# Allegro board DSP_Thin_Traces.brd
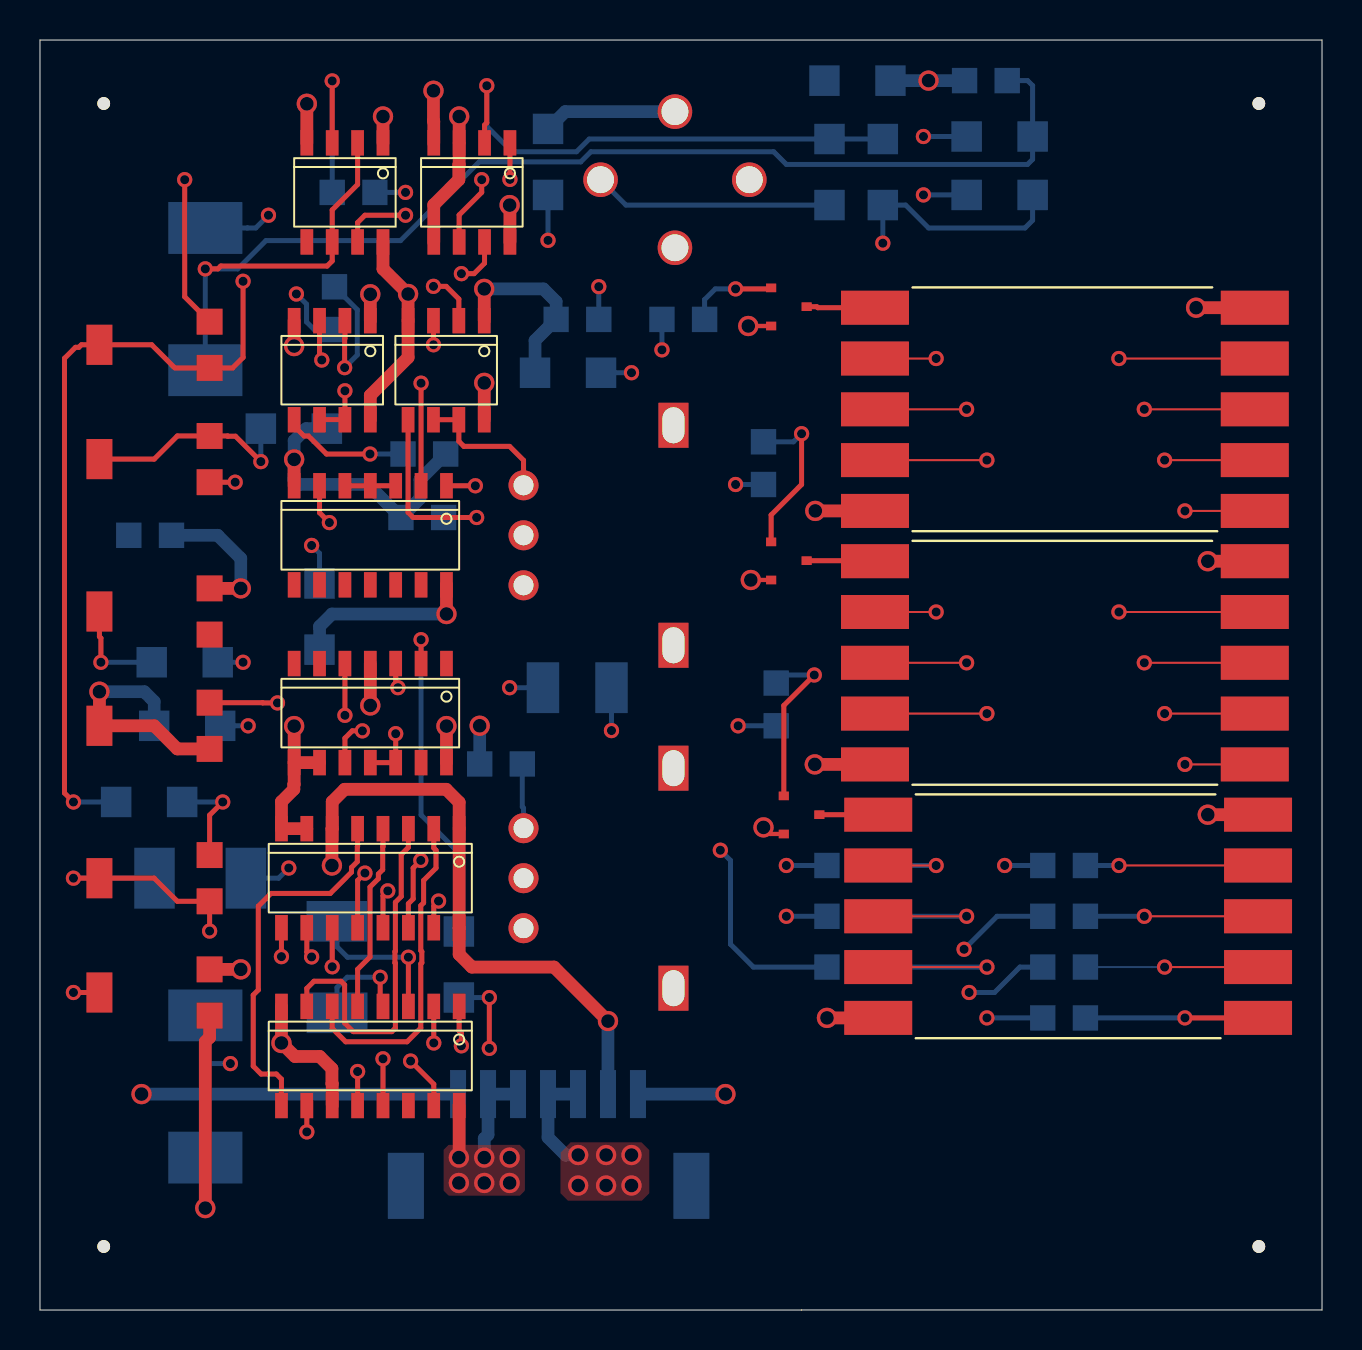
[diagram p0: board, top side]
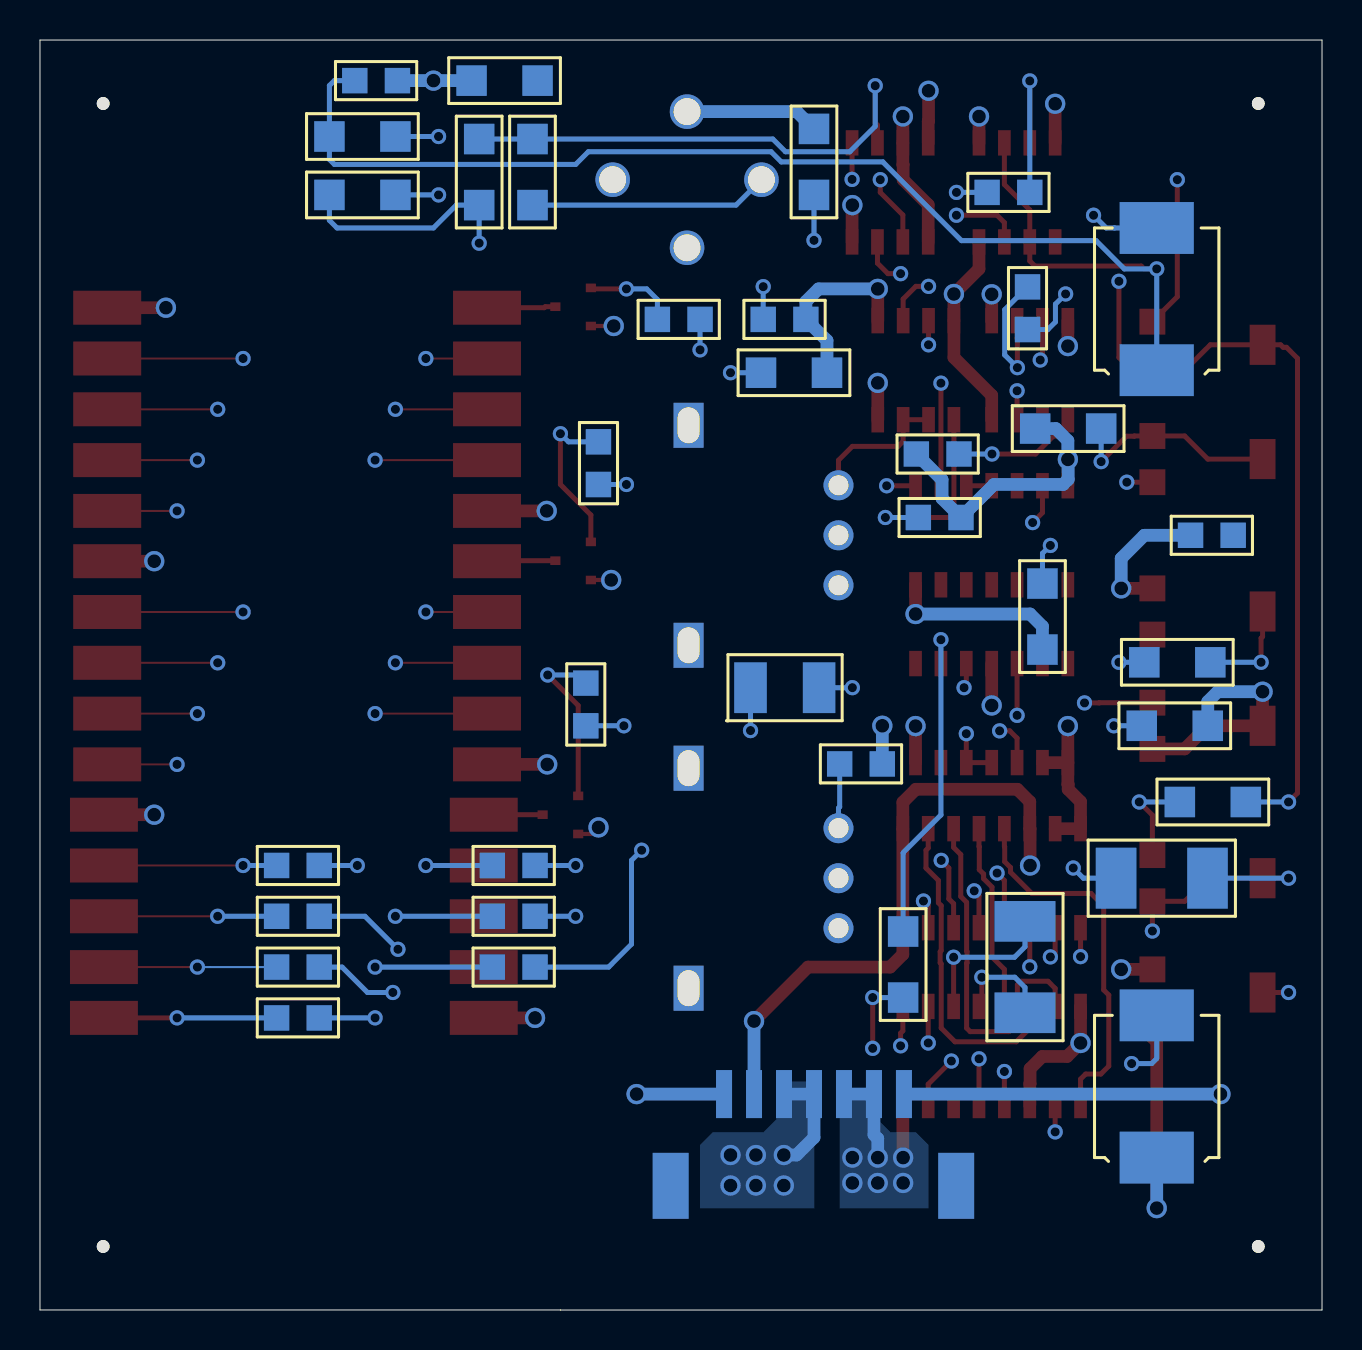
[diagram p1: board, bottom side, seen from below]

Outline 64.13 x 63.5 mm; copper layers: TOP, LAYER_2, LAYER_3, LAYER_4, LAYER_5, BOTTOM. Coordinates in mm from the lower left corner of the outline.
Outline path: 0,63.5 0,0 38.1,0 64.13,0 64.13,63.5 0,63.5

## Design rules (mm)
constraint set DEFAULT: 

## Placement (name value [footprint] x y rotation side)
C1  -  [SMC1210]  28.59 31.12 180 bottom
C2  -  [SMC1812]  5.73 21.59 0 bottom
C3  -  [SMC0805]  48.39 61.47 180 bottom
C4  -  [SMC0805]  4.45 38.74 0 bottom
C5  -  [SMC0805]  14.62 55.88 0 bottom
C6  -  [SMC0805]  27.95 49.53 180 bottom
C7  -  [SMC0805]  18.16 42.8 0 bottom
C8  -  [SMC0805]  14.73 49.02 90 bottom
C9  -  [SMC0805]  24.13 27.31 180 bottom
C10  -  [SMC0805]  20.19 39.63 180 bottom
C11  -  [SMC1812]  14.86 14.86 90 bottom
D1  -  [SMDO214AB12]  8.27 46.99 90 bottom
D2  -  [SMDO214AB12]  8.27 7.62 90 bottom
J1  -  [MDPC2A]  31.76 56.52 0 top
J2  -  [MLX1_5MM7P]  25.41 10.8 180 bottom
LED1  -  [LED-DISPLAY]  51.27 45.03 90 top
LED2  -  [LED-DISPLAY]  51.44 19.69 90 top
LED3  -  [LED-DISPLAY]  51.27 32.36 90 top
NOREF  -  [unnamed]  60.97 3.18 0 top
NOREF#2  -  [unnamed]  3.19 60.33 0 top
NOREF#3  -  [unnamed]  60.97 60.33 0 top
NOREF#4  -  [unnamed]  3.19 3.18 0 top
Q1  -  [SOT23]  37.47 50.17 0 top
Q2  -  [SOT23]  38.1 24.77 0 top
Q3  -  [SOT23]  37.47 37.47 0 top
R1  -  [3314G-]  5.73 42.55 270 top
R2  -  [SMR1206]  11.05 44.07 0 bottom
R3  -  [SMR1206]  39.5 55.25 90 bottom
R4  -  [3314G-]  5.73 34.93 270 top
R5  -  [SMR1206]  8.89 32.39 180 bottom
R6  -  [SMR1206]  42.16 58.55 270 bottom
R7  -  [SMR1206]  49.66 55.75 180 bottom
R8  -  [3314G-]  5.73 48.26 270 top
R9  -  [SMR1206]  3.81 25.4 0 bottom
R10  -  [3314G-]  5.73 21.59 270 top
R11  -  [SMR1206]  42.55 61.47 180 bottom
R12  -  [SMR1206]  25.41 59.06 270 bottom
R13  -  [SMR1206]  28.07 46.86 180 bottom
R14  -  [SMR1206]  20.95 18.92 270 bottom
R15  -  [3314G-]  5.73 15.88 270 top
R16  -  [3314G-]  5.73 29.21 270 top
R17  -  [SMR1206]  46.36 58.68 0 bottom
R18  -  [SMR1206]  5.71 29.21 0 bottom
R19  -  [RK09L]  27.94 38.74 270 top
R20  -  [RK09L]  27.94 21.59 270 top
R21  -  [SMR1206]  13.98 33.02 90 bottom
R22  -  [SMR0805]  50.16 22.23 0 bottom
R23  -  [SMR0805]  39.37 22.23 0 bottom
R24  -  [SMR0805]  39.37 19.69 0 bottom
R25  -  [SMR0805]  39.37 17.15 0 bottom
R26  -  [SMR0805]  50.16 19.69 0 bottom
R27  -  [SMR0805]  50.16 17.15 0 bottom
R28  -  [SMR0805]  50.16 14.61 0 bottom
R29  -  [SMR0805]  31.12 49.53 0 bottom
R30  -  [SMR0805]  36.83 29.21 90 bottom
R31  -  [SMR0805]  36.2 41.28 90 bottom
U2  ***  [SOIC8]  21.6 55.88 270 top
U3  ***  [SOIC14]  16.52 29.85 270 top
U4  ***  [SOIC14]  16.52 38.74 270 top
U5  ***  [SOIC8]  15.25 55.88 270 top
U6  ***  [SOIC8]  20.32 46.99 270 top
U7  ***  [SOIC8]  14.62 46.99 270 top
U8  ***  [SOIC16]  16.52 12.7 270 top
U9  ***  [SOIC16]  16.52 21.59 270 top

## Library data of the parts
C1 = 1000PF
C2 = 100PF
C3 C6 C9 = 1UF
C4 C5 C7 C8 C10 = 01UF
C11 = 001UF
D1 D2 = 1N914
J1 = MDPC2A
J2 = 7PINMLX
LED1-LED3 = LED-DISP
Q1-Q3 = 2N1305
R1 = IK-POT
R2 R7 R12 R13 R21 = RES10K
R3 R5 R6 R11 = RES100K
R4 = 10K-POT
R8 = 1M-POT
R9 = RES180K
R10 R15 = 50K-POT
R14 = RES510K
R16 = 3K-POT
R17 = RES15K
R18 = RES20K
R19 = 10K-VC
R20 = 1K-VC
R22-R28 = RES220
R29-R31 = RES1K
U2 = OPAMP
U3 = TVC-9400
U4 = NAND00
U5-U7 = 555
U8 = 3D-BCD
U9 = MC14543

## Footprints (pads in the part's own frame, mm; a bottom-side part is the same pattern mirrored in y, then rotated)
3314G-
  rect 2.007x1.295 smd: 1(0,-2.756)
  rect 1.295x1.295 smd: 2(-1.156,2.756) 3(1.156,2.756)
LED-DISPLAY
  rect 1.7x3.4 smd: 1(-5.08,-9.5) 2(-2.54,-9.5) 3(0,-9.5) 4(2.54,-9.5) 5(5.08,-9.5) 6(5.08,9.5) 7(2.54,9.5) 8(0,9.5) 9(-2.54,9.5) 10(-5.08,9.5)
MDPC2A
  round 1.727 hole 1.346: 1(0,-3.404) 2(0,3.404) 3(-3.721,0) 4(3.721,0)
MLX1_5MM7P
  rect 1.8x3.3 smd: (-7.172,-4.588) (7.112,-4.588)
  rect 0.8x2.4 smd: 1(-4.5,0) 2(-3,0) 3(-1.5,0) 4(0,0) 5(1.5,0) 6(3,0) 7(4.5,0)
RK09L
  rect 2.25x1.5 hole 1.8x1.1: (-5.5,3.75) (5.5,3.75)
  round 1.5 hole 1: 1(0,-3.75) 2(-2.5,-3.75) 3(2.5,-3.75)
SMC0805
  rect 1.27x1.27 smd: 1(0,0) 2(2.134,0)
SMC1210
  rect 1.626x2.54 smd: 1(0,0) 2(3.429,0)
SMC1812
  rect 2.032x3.048 smd: 1(0,0) 2(4.572,0)
SMDO214AB12
  rect 2.591x3.708 smd: 1(0,0) 2(7.112,0)
SMR0805
  rect 1.27x1.27 smd: 1(0,0) 2(2.134,0)
SMR1206
  rect 1.524x1.524 smd: 1(0,0) 2(3.302,0)
SOIC8
  rect 1.27x0.635 smd: 1(-2.477,1.905) 2(-2.477,0.635) 3(-2.477,-0.635) 4(-2.477,-1.905) 5(2.477,-1.905) 6(2.477,-0.635) 7(2.477,0.635) 8(2.477,1.905)
SOIC14
  rect 1.27x0.635 smd: 1(-2.477,3.81) 2(-2.477,2.54) 3(-2.477,1.27) 4(-2.477,0) 5(-2.477,-1.27) 6(-2.477,-2.54) 7(-2.477,-3.81) 8(2.477,-3.81) 9(2.477,-2.54) 10(2.477,-1.27) 11(2.477,0) 12(2.477,1.27) 13(2.477,2.54) 14(2.477,3.81)
SOIC16
  rect 1.27x0.635 smd: 1(-2.477,4.445) 2(-2.477,3.175) 3(-2.477,1.905) 4(-2.477,0.635) 5(-2.477,-0.635) 6(-2.477,-1.905) 7(-2.477,-3.175) 8(-2.477,-4.445) 9(2.477,-4.445) 10(2.477,-3.175) 11(2.477,-1.905) 12(2.477,-0.635) 13(2.477,0.635) 14(2.477,1.905) 15(2.477,3.175) 16(2.477,4.445)
SOT23
  rect 0.508x0.432 smd: 1(-0.889,0.94) 2(-0.889,-0.965) 3(0.889,0)
unnamed
  round 0.635 hole 3.175 unplated: (0,0)

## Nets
+5V: D2.1 J1.2 J2.5 J2.6 LED1.10 LED2.10 LED3.10 Q1.2 Q2.2 Q3.2 R12.1 R15.3 R16.1 R16.3 R18.1 R19.1 R19.3 R20.1 R20.3 R21.1 U3.14 U4.14 U5.4 U5.8 U6.4 U6.8 U7.4 U7.8 U8.16
+15V: J2.7 U2.8
-5V: J2.2 U3.4 U9.1 U9.6 U9.16
-15V: J2.1 U2.4
GND: C3.2 C4.2 C6.2 C7.2 C9.2 C10.2 J2.3 J2.4 LED1.5 LED2.5 LED3.5 R2.2 R4.2 R11.1 R13.2 R15.2 U2.3 U2.5 U3.8 U3.9 U4.7 U5.1 U6.1 U7.1 U8.8 U8.11 U9.7 U9.8
A: R31.1 U8.2
B: R30.1 U8.1
C: R29.1 U8.15
CLK1: C5.1 U4.2 U5.3
DSP0: LED1.1 LED2.1 LED3.1 R28.2
DSP1: LED1.2 LED2.2 LED3.2 R27.2
DSP2: LED1.3 LED2.3 LED3.3 R26.2
DSP3: LED1.4 LED2.4 LED3.4 R22.2
DSP4: LED1.9 LED2.9 LED3.9 R25.2
DSP5: LED1.8 LED2.8 LED3.8 R24.2
DSP6: LED1.7 LED2.7 LED3.7 R23.2
IN01: U4.6 U8.12
N001: U4.3 U4.4 U4.5
N002: C3.1 D1.1 R17.2 U5.2 U5.6
N003: D1.2 U5.7
N004: R16.2 R17.1
N005: R12.2 U3.10 U4.1
N006: Q1.1 R29.2
N007: Q2.1 R30.2
N007A: Q3.1 R31.2
N008: LED1.6 Q1.3
N008A: LED2.6 Q2.3
N008B: LED3.6 Q3.3
N009: R13.1 R14.1 U3.2
N010: R14.2 R15.1
N011: C1.1 U3.11 U3.12
N012: C2.2 U3.5
N013: C1.2 C2.1 R10.1 R10.3 U3.3
N014: R8.1 R8.3 R9.1 U2.7
N015: R9.2 R10.2
N016: R7.2 R8.2 U2.6
N017: R6.2 R7.1 U2.1
N018: R3.2 R5.1 R6.1 U2.2
N019: R4.1 R5.2
N100: C10.1 U6.5
N101: C7.1 U7.5
PRB1: J1.1 R1.3
PRB2: J1.3 R3.1
PRESET1: C5.2 D2.2 R18.2 U6.2
PRESET2: C8.2 R21.2 U7.2
PSP0: R28.1 U9.9
PSP1: R27.1 U9.10
PSP2: R26.1 U9.11
PSP3: R25.1 U9.12
PSP4: R24.1 U9.13
PSP5: R23.1 U9.14
PSP6: R22.1 U9.15
PST+: C11.1 U8.4
PST-: C11.2 U8.3
SET1: C6.1 R19.2 U6.6 U6.7
SET2: C9.1 R20.2 U7.6 U7.7
SNSR1: R1.1 R1.2 R2.1
SP0: U8.9 U9.5
SP01: U8.7 U9.3
SP02: U8.6 U9.2
SP03: U8.5 U9.4
T1: U7.3 U8.13
T2: C8.1 U6.3 U8.10

Pads without a net: C4 1; J1 4; R4 3; R11 2; U3 1 6 7 13; U4 8 9 10 11 12 13; U5 5; U8 14

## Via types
v1: diameter 0.762, hole 0.457, TOP to BOTTOM, 100 vias
v2: diameter 1.016, hole 0.686, TOP to BOTTOM, 47 vias

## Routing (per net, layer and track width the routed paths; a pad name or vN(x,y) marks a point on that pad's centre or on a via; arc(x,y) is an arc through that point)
+5V: length 76.3
  TOP w0.21: v2(35.56,36.5) Q3.2 ; Q2.2 36.53,23.8 v2(36.2,24.13) ; v2(35.43,49.2) Q1.2
  TOP w0.635: U3.14 v2(20.33,29.2) ; U4.14 v2(20.33,34.8) ; U6.8 v2(22.23,46.36) ; U5.8 17.16,52.06 v2(18.41,50.8) U6.4 18.41,47.63 16.52,45.74 U7.8 ; U5.4 v2(13.35,60.31) ; LED3.10 v2(38.76,27.28) ; U7.4 v2(12.71,48.2) ; v2(2.97,30.91) R16.1 R18.1 6.87,28.06 R16.3 ; 41.93,14.61 v2(39.37,14.61) ; v2(20.95,7.62) 20.97,7.64 U8.16 ; LED1.10 v2(38.79,39.95) ; v2(8.27,5.1) 8.27,13.41 8.49,13.63 R15.3
  BOTTOM w0.635: J2.5 J2.6 22.41,8.76 22.23,8.57 v2(22.23,7.62) ; D2.1 v2(8.27,5.1) ; R21.1 13.98,34.18 14.61,34.8 v2(20.33,34.8) ; R12.1 26.28,59.92 J1.2 ; v2(2.97,30.91) 5.22,30.91 5.71,30.42 R18.1
  vias: v2(20.95,6.35) v2(22.23,6.35) v2(23.5,7.62) v2(23.5,6.35)
+15V: length 81.4
  TOP w0.635: v2(23.5,55.25) 23.51,55.23 U2.8
  LAYER_4 w0.635: v2(5.08,10.8) 5.08,54.61 5.97,55.5 7.5,55.5 7.88,55.88 17.01,55.88 17.91,56.78 18.66,56.78 20.2,55.25 v2(23.5,55.25)
  BOTTOM w0.635: J2.7 v2(5.08,10.8)
-5V: length 43.4
  TOP w0.635: U3.4 v2(16.52,30.23) ; v2(14.61,22.23) 14.61,24.05 U9.6 14.62,25.42 15.24,26.04 20.32,26.04 20.97,25.39 U9.1 U9.16 20.97,17.78 21.6,17.15 25.71,17.15 v2(28.41,14.45)
  LAYER_3 w0.635: v2(16.52,30.23) 16.02,30.74 14.67,30.74 13.93,30 13.93,22.9 v2(14.61,22.23)
  BOTTOM w0.635: J2.2 v2(28.41,14.45)
-15V: length 145.8
  TOP w0.635: U2.4 19.7,59.44 19.68,59.45 v2(19.68,60.96)
  LAYER_3 w0.635: v2(19.68,60.96) 20.95,62.23 43.76,62.23 44.02,62.5 44.88,62.5 45.14,62.23 57.15,62.23 57.78,61.6 57.78,57.79 58.42,57.15 62.23,57.15 62.87,56.52 62.87,6.99 62.23,6.35 58.42,6.35 57.78,5.72 57.78,1.91 57.15,1.27 37.8,1.27 arc(37.49,1.33) 37.23,1.51 34.53,4.21 arc(34.35,4.47) 34.29,4.78 v2(34.29,10.8)
  BOTTOM w0.635: 29.91,10.8 v2(34.29,10.8)
GND: length 76.5
  TOP w0.635: R4.2 v2(10.05,36.08) ; U9.7 U9.8 12.08,25.42 12.7,26.04 12.7,26.28 12.71,26.29 U3.8 ; U2.5 19.7,55.26 20.95,56.52 20.95,57.26 20.97,57.28 U2.3 v2(20.97,59.68) ; U3.8 U3.9 ; U3.8 v2(12.71,29.2) ; U6.1 v2(22.23,51.06) ; U8.8 v2(12.08,13.35) 12.75,12.68 13.99,12.68 14.61,12.07 14.61,11.32 14.62,11.3 U8.11 ; U7.1 v2(16.52,50.79) ; LED1.5 v2(57.84,50.11) ; U5.1 v2(17.16,59.68) ; R15.2 v2(10.05,17.03) ; LED2.5 v2(58.42,24.77) ; U4.7 v2(12.71,42.53) ; LED3.5 v2(58.42,37.44)
  BOTTOM w0.635: v2(10.05,36.08) 10.05,37.58 8.89,38.74 C4.2 ; R13.2 24.77,48.47 C6.2 25.82,50.42 25.19,51.06 v2(22.23,51.06) ; C7.2 19.01,41.51 19.01,40.57 C10.2 16.41,41.28 12.95,41.28 12.7,41.53 12.7,42.52 v2(12.71,42.53) 12.71,43.47 13.32,44.07 R2.2 ; 26.91,7.76 v2(26.92,7.75) 26.29,7.75 25.41,8.62 J2.4 J2.3 ; C3.2 v2(44.45,61.47) R11.1 ; v2(22,29.21) C9.2
  vias: v2(26.92,6.22) v2(28.32,7.75) v2(28.32,6.22) v2(29.59,7.75) v2(29.59,6.22)
A: length 39.1
  TOP w0.25: U8.2 v1(19.7,13.35)
  LAYER_2 w0.25: v1(34.8,41.28) 33.91,40.39 33.91,26.04 24.51,16.64 21.54,16.64 19.7,14.8 v1(19.7,13.35)
  BOTTOM w0.25: R31.1 v1(34.8,41.28)
B: length 26.5
  TOP w0.25: U8.1 20.97,13.95 21.08,13.84 v1(21.08,13.21)
  LAYER_2 w0.25: v1(21.08,13.21) 22.35,14.48 23.75,14.48 34.93,25.66 v1(34.93,29.21)
  BOTTOM w0.25: R30.1 v1(34.93,29.21)
C: length 46.6
  TOP w0.25: U8.15 19.7,11.29 v1(18.54,12.45)
  LAYER_2 w0.25: v1(31.12,48.01) 31.12,46.61 30.23,45.72 30.23,23.37 24.51,17.65 21.84,17.65 18.54,14.35 v1(18.54,12.45)
  BOTTOM w0.25: R29.1 v1(31.12,48.01)
CLK1: length 31.9
  TOP w0.25: v1(14.62,61.45) U5.3 ; U4.2 v1(19.06,46.34)
  LAYER_2 w0.25: v1(19.06,46.34) 20.41,47.69 20.41,54.78 14.62,60.57 v1(14.62,61.45)
  BOTTOM w0.25: C5.1 v1(14.62,61.45)
DSP0: length 41
  TOP w0.101: LED1.1 v1(57.28,39.95) ; LED3.1 v1(57.28,27.28)
  TOP w0.25: LED2.1 v1(57.28,14.61)
  LAYER_2 w0.101: v1(57.28,14.61) v1(57.28,27.28) v1(57.28,39.95)
  BOTTOM w0.25: R28.2 v1(57.28,14.61)
DSP1: length 43
  TOP w0.101: LED2.2 57.02,17.15 57.02,17.15 v1(56.26,17.15) ; LED1.2 v1(56.26,42.49) ; LED3.2 v1(56.26,29.82)
  LAYER_2 w0.101: v1(56.26,17.15) v1(56.26,29.82) v1(56.26,42.49)
  BOTTOM w0.101: R27.2 55.63,17.15 55.63,17.15 v1(56.26,17.15)
DSP2: length 45
  TOP w0.101: LED1.3 v1(55.24,45.03) ; LED3.3 v1(55.24,32.36) ; LED2.3 v1(55.24,19.69)
  LAYER_2 w0.101: v1(55.24,45.03) v1(55.24,32.36) v1(55.24,19.69)
  BOTTOM w0.25: R26.2 v1(55.24,19.69)
DSP3: length 47.6
  TOP w0.101: LED2.4 v1(53.98,22.23) ; LED3.4 v1(53.98,34.9) ; LED1.4 v1(53.98,47.57)
  LAYER_2 w0.101: v1(53.98,22.23) v1(53.98,34.9) v1(53.98,47.57)
  BOTTOM w0.25: R22.2 v1(53.98,22.23)
DSP4: length 47.9
  TOP w0.101: 41.93,17.15 v1(47.37,17.15) ; LED3.9 v1(47.37,29.82) ; LED1.9 v1(47.37,42.49)
  LAYER_2 w0.101: v1(47.37,42.49) v1(47.37,29.82) v1(47.37,17.15)
  BOTTOM w0.25: R25.2 v1(47.37,17.15)
DSP5: length 43.8
  TOP w0.101: LED1.8 v1(46.36,45.03) ; 41.93,19.69 v1(46.36,19.69) ; LED3.8 v1(46.36,32.36)
  LAYER_2 w0.101: v1(46.36,19.69) v1(46.36,32.36) v1(46.36,45.03)
  BOTTOM w0.25: R24.2 v1(46.36,19.69)
DSP6: length 37.7
  TOP w0.101: LED1.7 v1(44.83,47.57) ; LED3.7 v1(44.83,34.9) ; 41.93,22.23 v1(44.83,22.23)
  LAYER_2 w0.101: v1(44.83,22.23) v1(44.83,34.9) v1(44.83,47.57)
  BOTTOM w0.25: R23.2 v1(44.83,22.23)
IN01: length 34.3
  TOP w0.25: U4.6 13.98,39.87 v1(14.48,39.37) ; U8.12 v1(15.89,11.92)
  LAYER_2 w0.25: v1(15.89,11.92) 15.89,21.26 15.58,21.57 15.58,22.12 15.89,22.43 15.89,25.54 18.58,28.23 18.58,31.84 14.48,35.94 v1(14.48,39.37)
N001: length 2.5
  TOP w0.25: U4.5 U4.4 U4.3
N002: length 67.3
  TOP w0.25: v1(8.27,52.06) 8.9,52.06 9.04,52.2 14.37,52.2 14.62,52.45 U5.6 14.62,55.01 15.89,56.28 U5.2
  BOTTOM w0.25: D1.1 v1(8.27,52.06) 9.89,52.06 11.3,53.47 18.03,53.47 21.97,57.41 27.05,57.41 27.56,57.91 36.7,57.91 37.34,57.28 49.4,57.28 49.66,57.53 R17.2 49.66,61.22 49.41,61.47 C3.1
N003: length 13.8
  TOP w0.25: v1(18.29,54.74) 16.26,54.74 15.89,54.37 U5.7
  LAYER_5 w0.25: v1(18.29,54.74) v1(11.43,54.74)
  BOTTOM w0.25: D1.2 10.38,54.1 10.38,54.1 10.79,54.1 v1(11.43,54.74)
N004: length 72.8
  TOP w0.25: v1(11.88,30.35) 11.15,30.35 11.13,30.37 R16.2
  LAYER_5 w0.25: v1(11.88,30.35) 11.88,27.87 14.08,25.67 40.79,25.67 43.94,28.83 43.94,54.23 44.82,55.11 44.82,58.05 v1(44.2,58.68)
  BOTTOM w0.25: R17.1 v1(44.2,58.68)
N005: length 37.6
  TOP w0.25: v1(16.13,28.96) 15.62,28.96 15.25,28.59 U3.10 ; U4.1 v1(21.78,41.21)
  LAYER_2 w0.25: v1(25.41,53.48) 25.41,47.51 21.78,43.88 v1(21.78,41.21)
  LAYER_5 w0.25: v1(21.78,41.21) 21.14,41.21 21.08,41.15 19.3,41.15 14.58,36.43 14.58,29.46 15.08,28.96 v1(16.13,28.96)
  BOTTOM w0.25: R12.2 v1(25.41,53.48)
N006: length 4.6
  TOP w0.25: Q1.1 36.53,51.06 v1(34.8,51.06)
  BOTTOM w0.25: R29.2 33.25,50.52 33.78,51.06 v1(34.8,51.06)
N007: length 8.7
  TOP w0.25: v1(38.73,31.75) 37.21,30.23 Q2.1
  BOTTOM w0.25: R30.2 37.24,31.75 v1(38.73,31.75)
N007A: length 8.1
  TOP w0.25: Q3.1 36.58,39.75 38.1,41.28 v1(38.1,43.82)
  BOTTOM w0.25: v1(38.1,43.82) 37.69,43.41 R31.2
N008: length 3.4
  TOP w0.25: LED1.6 38.91,50.11 38.86,50.17 Q1.3
N008A: length 2.9
  TOP w0.25: Q2.3 LED2.6
N008B: length 3.4
  TOP w0.25: Q3.3 41.75,37.47 LED3.6
N009: length 38
  TOP w0.25: U3.2 v1(19.06,33.51)
  LAYER_2 w0.25: v1(29.59,46.86) 27.18,46.86 22.86,42.55 22.86,35.94 20.43,33.51 v1(19.06,33.51)
  BOTTOM w0.25: R14.1 20.95,22.86 19.06,24.75 v1(19.06,33.51) ; v1(29.59,46.86) R13.1
N010: length 27.4
  TOP w0.25: v1(22.48,13.08) v1(22.48,15.62) ; 2.97,15.88 v1(1.67,15.88)
  LAYER_5 w0.25: v1(1.67,15.88) 2.12,15.43 2.12,15.28 3.21,14.19 21.37,14.19 v1(22.48,13.08)
  BOTTOM w0.25: R14.2 v1(22.48,15.62)
N011: length 16.1
  TOP w0.25: v1(17.79,28.82) U3.12 U3.11
  LAYER_5 w0.25: v1(28.59,28.97) 27.94,28.32 19.18,28.32 18.68,28.82 v1(17.79,28.82)
  BOTTOM w0.25: C1.1 v1(28.59,28.97)
N012: length 13.7
  TOP w0.25: U3.5 v1(15.25,29.73)
  LAYER_2 w0.25: v1(15.25,29.73) 15.25,26.69 12.45,23.88 v1(12.45,22.1)
  BOTTOM w0.25: C2.2 11.94,21.59 v1(12.45,22.1)
N013: length 38.8
  TOP w0.25: U3.3 17.79,31.23 v1(17.91,31.12) ; v1(8.49,18.95) R10.3 6.87,20.44 5.71,21.59 R10.1 v1(1.67,21.59)
  LAYER_2 w0.25: v1(8.49,18.95) 8.49,22.84 14.1,28.45 14.1,29.72 15.49,31.12 v1(17.91,31.12)
  LAYER_5 w0.25: v1(23.5,31.12) v1(17.91,31.12)
  BOTTOM w0.25: C2.1 v1(1.67,21.59) ; v1(23.5,31.12) 23.75,31.12 C1.2
N014: length 52.4
  TOP w0.25: U2.7 22.24,52.34 21.71,51.82 v1(21.08,51.82) ; v1(1.67,25.4) 1.23,25.85 1.23,47.58 1.78,48.13 1.95,48.13 2.07,48.26 R8.1 5.59,48.26 6.74,47.11 R8.3 9.64,47.11 10.16,47.63 v1(10.16,51.44)
  LAYER_5 w0.25: v1(10.16,51.44) 11.3,52.58 20.32,52.58 v1(21.08,51.82)
  BOTTOM w0.25: R9.1 v1(1.67,25.4)
N015: length 5
  TOP w0.25: R10.2 8.49,24.74 v1(9.14,25.4)
  BOTTOM w0.25: R9.2 v1(9.14,25.4)
N016: length 52.2
  TOP w0.25: v1(7.24,56.52) 7.24,50.66 R8.2 ; U2.6 20.97,54.75 22.1,55.88 v1(22.1,56.52)
  LAYER_5 w0.25: v1(44.2,55.75) 41.53,58.42 24,58.42 v1(22.1,56.52) 18.6,56.52 18.57,56.55 18.01,56.55 17.97,56.52 v1(7.24,56.52)
  BOTTOM w0.25: R7.2 v1(44.2,55.75)
N017: length 33.1
  TOP w0.25: U2.1 v1(23.51,56.53)
  LAYER_5 w0.25: v1(42.16,53.34) 40.51,54.99 27.18,54.99 25.64,56.53 v1(23.51,56.53)
  BOTTOM w0.25: R7.1 49.66,54.48 49.28,54.1 44.45,54.1 43.31,55.25 R6.2 v1(42.16,53.34)
N018: length 68.7
  TOP w0.25: U2.2 22.24,59.25 22.35,59.36 v1(22.35,61.22)
  LAYER_2 w0.25: v1(10.16,32.39) 9.02,33.53 9.02,58.42 12.83,62.23 21.34,62.23 v1(22.35,61.22)
  BOTTOM w0.25: v1(22.35,61.22) 22.35,59.18 23.62,57.91 26.84,57.91 27.48,58.55 R3.2 R6.1 ; v1(10.16,32.39) R5.1
N019: length 5.1
  TOP w0.25: R4.1 2.97,33.67 3.05,33.6 v1(3.05,32.39)
  BOTTOM w0.25: R5.2 v1(3.05,32.39)
N100: length 9.8
  TOP w0.25: v1(21.84,39.63) 18.67,39.63 18.41,39.88 U6.5
  BOTTOM w0.25: C10.1 v1(21.84,39.63)
N101: length 6.3
  TOP w0.25: U7.5 12.71,44.2 13.21,43.7 13.43,43.7 14.33,42.8 v1(16.51,42.8)
  BOTTOM w0.25: C7.1 v1(16.51,42.8)
PRB1: length 39.8
  TOP w0.25: R1.3 v1(9.77,41.39)
  LAYER_5 w0.25: J1.1 30.77,54.1 25.68,54.1 25.67,54.11 25.16,54.11 25.15,54.1 8.64,54.1 7.11,52.58 7.11,43.05 8.78,41.39 v1(9.77,41.39)
PRB2: length 12
  BOTTOM w0.25: R3.1 29.31,55.25 J1.3
PRESET1: length 66.1
  TOP w0.25: v1(19.68,51.18) 20.32,51.18 20.95,50.55 U6.2
  LAYER_2 w0.25: v1(18.29,55.88) 19.68,54.48 v1(19.68,51.18) ; v1(10.41,29.21) 7.3,26.1 7.3,16.45 9.53,14.23 v1(9.53,12.32)
  LAYER_5 w0.25: v1(19.68,51.18) 19.23,51.64 11.76,51.64 9.91,49.79 9.91,42.2 10.54,41.57 10.54,37.76 9.21,36.43 9.21,30.42 v1(10.41,29.21)
  BOTTOM w0.25: R18.2 v1(10.41,29.21) ; C5.2 v1(18.29,55.88) ; D2.2 8.27,12.57 8.52,12.32 v1(9.53,12.32)
PRESET2: length 18.8
  TOP w0.25: U7.2 15.25,48.58 15.24,48.56 v1(15.24,47.12)
  LAYER_2 w0.25: v1(15.24,47.12) 14.58,46.46 14.58,41.76 13.59,40.77 v1(13.59,38.23)
  BOTTOM w0.25: R21.2 13.98,37.83 v1(13.59,38.23) ; 14.73,51.16 15.88,50.01 15.88,47.75 v1(15.24,47.12)
PSP0: length 43.2
  TOP w0.25: U9.9 v1(12.08,17.67)
  LAYER_5 w0.25: v1(12.08,17.67) 12.08,17.03 12.06,17.02 12.06,15.5 12.57,14.99 21.72,14.99 23.5,13.21 40.89,13.21 42.29,14.61 v1(47.37,14.61)
  BOTTOM w0.25: R28.1 v1(47.37,14.61)
PSP1: length 41.8
  TOP w0.25: v1(13.59,17.65) 13.35,17.89 U9.10
  LAYER_5 w0.25: v1(46.48,15.88) 37.47,15.88 35.81,14.23 30.61,14.23 28.54,16.3 20.87,16.3 20.45,15.88 14.22,15.88 13.59,16.51 v1(13.59,17.65)
  BOTTOM w0.25: R27.1 49.02,17.15 47.75,15.88 v1(46.48,15.88)
PSP2: length 39.9
  TOP w0.25: U9.11 v1(14.62,17.16)
  LAYER_5 w0.25: v1(46.23,18.04) 29.34,18.04 28.19,16.89 20.83,16.89 19.18,18.54 16,18.54 v1(14.62,17.16)
  BOTTOM w0.25: v1(46.23,18.04) 47.88,19.69 R26.1
PSP3: length 31.5
  TOP w0.25: v1(16.26,21.85) 15.89,21.48 U9.12
  LAYER_5 w0.25: v1(16.26,21.85) 17.56,23.15 19.33,23.15 19.49,22.99 v1(34.04,22.99)
  BOTTOM w0.25: R25.1 35.69,17.15 34.54,18.29 34.54,22.48 v1(34.04,22.99)
PSP4: length 26.3
  TOP w0.25: v1(17.4,20.96) 17.16,20.72 U9.13
  LAYER_5 w0.25: v1(17.4,20.96) 18.03,20.96 18.2,21.12 20.79,21.12 21.97,19.94 21.97,19.31 23.27,18.01 26.39,18.01 28.07,19.69 v1(37.34,19.69)
  BOTTOM w0.25: R24.1 v1(37.34,19.69)
PSP5: length 25.5
  TOP w0.25: v1(19.05,22.48) 18.67,22.1 18.67,20.56 18.43,20.32 U9.14
  LAYER_5 w0.25: v1(19.05,22.48) 20.95,22.48 22.99,20.45 27.05,20.45 28.83,22.23 v1(37.34,22.23)
  BOTTOM w0.25: v1(37.34,22.23) 38.35,22.23 38.35,22.23 R23.1
PSP6: length 37.1
  TOP w0.25: v1(19.94,20.45) 19.7,20.21 U9.15
  LAYER_5 w0.25: v1(19.94,20.45) 19.94,18.67 21.21,17.4 27.56,17.4 28.96,18.8 46.74,18.8 48.26,20.32 v1(48.26,22.23)
  BOTTOM w0.25: v1(48.26,22.23) 49.15,22.23 49.15,22.23 R22.1
PST+: length 5.2
  TOP w0.25: U8.4 17.02,15.32 v1(17.02,16.64)
  BOTTOM w0.25: v1(17.02,16.64) 15.37,16.64 14.86,16.13 C11.1
PST-: length 7.5
  TOP w0.25: U8.3 v1(18.43,17.64)
  BOTTOM w0.25: C11.2 14.86,18.16 15.38,17.64 v1(18.43,17.64)
SET1: length 20.4
  TOP w0.25: R19.2 24.19,42.49 23.5,43.18 21.21,43.18 20.95,43.43 U6.7 U6.6
  LAYER_5 w0.25: R19.2 24.19,47.4 v1(27.95,51.17)
  BOTTOM w0.25: C6.1 v1(27.95,51.17)
SET2: length 42.6
  TOP w0.25: v1(15.25,45.96) U7.7 U7.6
  LAYER_5 w0.25: R20.2 13.63,24.09 11.09,26.63 11.09,41.58 11.67,42.16 11.67,44.82 12.81,45.96 v1(15.25,45.96)
  BOTTOM w0.25: C9.1 24.13,25.15 24.19,25.09 R20.2
SNSR1: length 10.7
  TOP w0.25: R1.1 5.71,42.55 6.87,43.7 R1.2 9.39,43.7 9.4,43.69 9.78,43.69 v1(11.05,42.42)
  BOTTOM w0.25: R2.1 v1(11.05,42.42)
SP0: length 18.8
  TOP w0.25: U8.9 12.08,11.54 11.83,11.8 11.06,11.8 10.67,12.19 10.67,15.75 10.92,16 10.92,20.19 11.56,20.83 14.52,20.83 15.58,21.89 15.58,22.12 15.88,22.42 15.88,23.16 15.89,23.18 U9.5
SP01: length 18
  TOP w0.25: U9.3 18.43,23.13 18.07,22.77 18.07,20.68 17.78,20.39 17.78,17.94 17.76,17.92 17.76,17.36 17.78,17.34 17.78,14.1 17.6,13.92 15.67,13.92 15.24,14.35 15.24,16.26 15.06,16.44 13.71,16.44 13.35,16.08 U8.7
SP02: length 16.5
  TOP w0.25: U9.2 19.7,23.1 19.81,22.99 19.81,22.1 19.19,21.48 19.19,20.36 19.05,20.22 19.05,17.97 19.1,17.92 19.1,17.36 19.05,17.31 19.05,14.1 18.36,13.41 15.29,13.41 14.62,14.08 U8.6
SP03: length 9.4
  TOP w0.25: U9.4 17.16,23.18 17.14,23.16 17.14,22.02 16.93,21.8 16.93,21.57 16.51,21.15 16.51,17.65 15.89,17.03 U8.5
T1: length 44.4
  TOP w0.25: v1(14.1,47.5) 13.98,47.61 U7.3 ; U8.13 v1(17.16,12.56)
  LAYER_2 w0.25: v1(17.16,12.56) 17.69,13.09 17.69,19.71 16.73,20.68 16.73,21.24 17.16,21.67 17.16,25.54 19.09,27.47 19.09,32.54 15.84,35.79 15.84,45.59 15.93,45.68 15.93,47.45 15.49,47.88 14.48,47.88 v1(14.1,47.5)
T2: length 61.1
  TOP w0.25: U8.10 v1(13.35,8.91) ; U6.3 v1(19.68,48.26)
  LAYER_2 w0.25: v1(13.35,8.91) 13.35,13.96 11.81,15.5 9.78,15.5 7.81,17.46 7.81,25.72 11.26,29.16 11.26,39.58 11.81,40.13 11.81,49.79 v1(12.83,50.8)
  LAYER_5 w0.25: v1(12.83,50.8) 13.97,50.8 16.51,48.26 v1(19.68,48.26)
  BOTTOM w0.25: v1(12.83,50.8) 13.34,50.29 13.34,49.4 13.72,49.02 C8.1

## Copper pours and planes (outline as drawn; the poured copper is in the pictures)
+5V on TOP: 20.19,8 20.45,8.26 24,8.26 24.26,8 24.26,5.97 24,5.72 20.45,5.72 20.19,5.97
+5V on BOTTOM: 24.13,10.8 24.13,5.08 19.68,5.08 19.68,8.26 20.32,8.89 21.59,8.89 22.23,9.53 22.23,10.8
+5V on LAYER_4: 1.14,62.36 1.14,1.02 63.5,1.02 63.5,62.36
GND on TOP: 26.42,5.46 30.1,5.46 30.48,5.84 30.48,8 30.1,8.38 26.54,8.38 26.04,7.88 26.04,5.84
GND on BOTTOM: 25.4,11.43 25.4,5.08 31.12,5.08 31.12,8.26 30.48,8.89 27.94,8.89 27.3,9.53 27.3,11.43
GND on LAYER_3: 0.65,0.76 0.65,62.74 63.37,62.74 63.37,0.76 ; 5 cut-outs

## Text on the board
XSECTION_CHART: *  SURFACE - AIR | * SOLDERMASK_TOP MASK - POLYIMIDE | * PASTEMASK_TOP MASK - POLYIMIDE | L1 TOP CONDUCTOR - HALF_OZ_COPPER | *  DIELECTRIC - FR-4 | L2 LAYER_2 CONDUCTOR - HALF_OZ_COPPER | *  DIELECTRIC - FR-4_NO_FLOW_PREPREG | L3 LAYER_3 CONDUCTOR - HALF_OZ_COPPER | *  DIELECTRIC - POLYIMIDE_FILM_1MIL | L4 LAYER_4 CONDUCTOR - HALF_OZ_COPPER | *  DIELECTRIC - POLYIMIDE | L5 LAYER_5 CONDUCTOR - HALF_OZ_COPPER | L6 BOTTOM CONDUCTOR - HALF_OZ_COPPER | * PASTEMASK_BOTTOM MASK - POLYIMIDE | * SOLDERMASK_BOTTOM MASK - POLYIMIDE | * COVERLAY_INTERNAL_3 MASK - POLYIMIDE_FILM_1MIL | * COVERLAY_INTERNAL_4 MASK - POLYIMIDE_FILM_1MIL | * SOLDERMASK_INT_2 MASK - SOLDERMASK_FLEXIBLE_LPI | * SOLDERPASTE_INT_2 MASK - SOLDER_PASTE_SAC | * SOLDERPASTE_INT_5 MASK - SOLDER_PASTE_SAC | * SOLDERMASK_INT_5 MASK - SOLDERMASK_FLEXIBLE_LPI | PRIMARY | __________ | 48.381 MIL | RIGID-4-LAYER | 30.981 MIL | FLEX-2-LAYER | 4.4 MIL | 1-6 | 2-5 | Sensor Controller Stackup | Unit = mils | # | 1 | 2 | 3 | 4 | 5 | 6 | NAME | SOLDERMASK_TOP | PASTEMASK_TOP | SOLDERMASK_INT_2 | SOLDERPASTE_INT_2 | COVERLAY_INTERNAL_3 | TOP | LAYER_2 | LAYER_3 | LAYER_4 | LAYER_5 | BOTTOM | COVERLAY_INTERNAL_4 | SOLDERPASTE_INT_5 | SOLDERMASK_INT_5 | PASTEMASK_BOTTOM | SOLDERMASK_BOTTOM | TYPE | SURFACE | MASK | CONDUCTOR | DIELECTRIC | MATERIAL | AIR | POLYIMIDE | SOLDERMASK_FLEXIBLE_LPI | SOLDER_PASTE_SAC | POLYIMIDE_FILM_1MIL | HALF_OZ_COPPER | FR-4 | FR-4_NO_FLOW_PREPREG | TOLERANCE | +0/-0 | +0.05/-0.05 | TOTAL THICKNESS | ZONE NAME | 0.000 | 0.591 | 3.000 | 0.700 | 8.000 | 2.000 | 1.000 | 30.981 | DISPLAY_4L | PROBE_PANEL_4L | 48.381 | ZONE_1 | 4.400 | FLEX_ZONE_1
